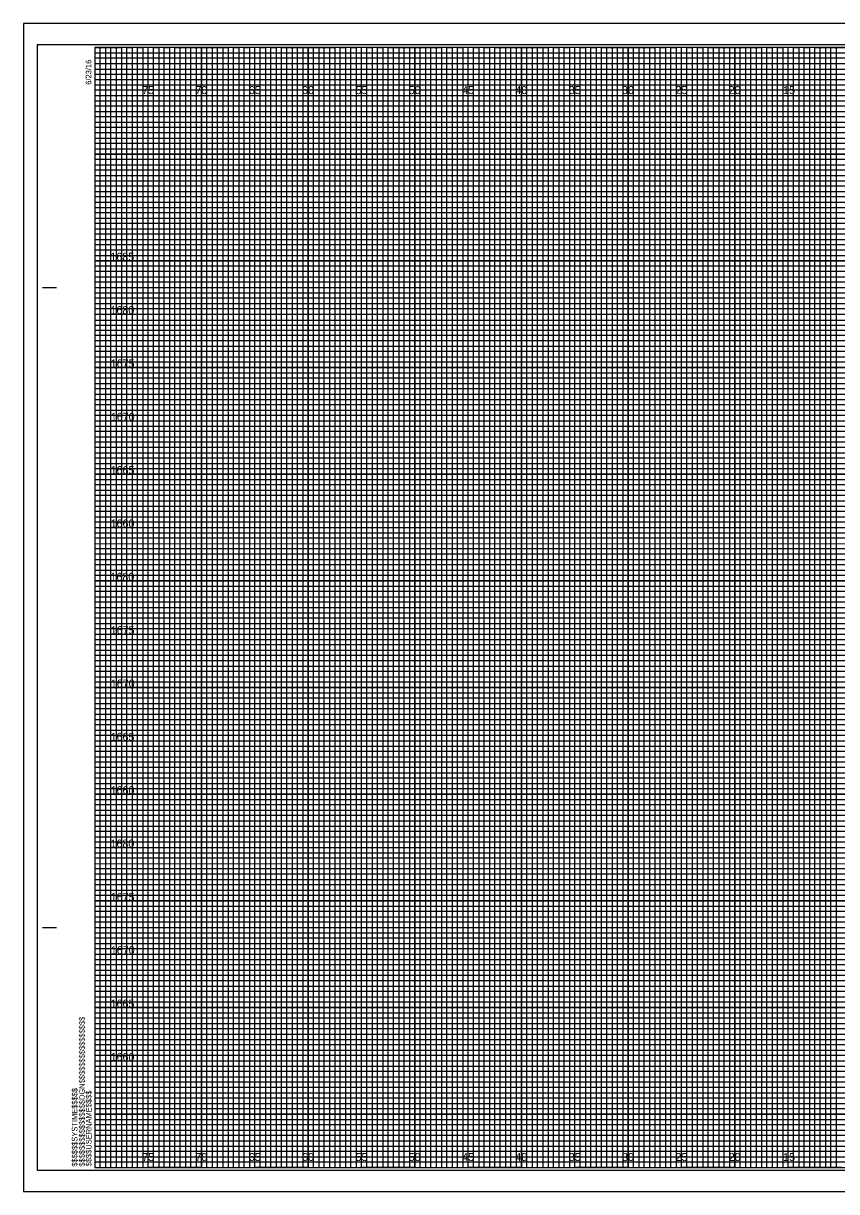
# Model space of a CAD drawing. Extents: x -7 to 162, y -2 to 327.
# Drawn here: x -6.7 to 69.5, y 217.7 to 327.2 of the extents above; entities that cross this region are included whole.
import ezdxf

# ---------------------------------------------------------------- set-up
doc = ezdxf.new("R2010")
doc.units = 0
for name, color, linetype in [('Raster_Level_0', 7, 'Continuous'), ('Scratch_Level_3', 7, 'Continuous'), ('Sheet Cross Section CELL', 7, 'Continuous'), ('Sheet Cross Section Grid Major CELL', 7, 'Continuous'), ('Sheet Cross Section Grid Middle CELL', 7, 'Continuous'), ('Sheet Cross Section Grid Minor 1 CELL', 7, 'Continuous'), ('Sheet Cross Section Grid Minor 2 CELL', 7, 'Continuous'), ('Sheet Cutting Line CELL', 7, 'Continuous'), ('Sheet DOT Grid CELL', 7, 'Continuous'), ('Sheet Plot Border Inside CELL', 7, 'Continuous'), ('Sheet Plot Border Outside CELL', 7, 'Continuous')]:
    doc.layers.add(name, color=color, linetype=linetype)

msp = doc.modelspace()

# ---------------------------------------------------------------- linework, layer by layer
at = {"layer": 'Sheet Cross Section CELL'}
for p, q in [((-4.9, 302.5), (-3.65, 302.5)), ((-4.85, 302.5), (-3.6, 302.5)), ((-4.9, 242.5), (-3.65, 242.5)), ((-4.85, 242.5), (-3.6, 242.5)), ((0, 220), (0, 220)), ((0, 220), (0, 220)), ((0, 220), (0, 220)), ((0, 220), (0, 220)), ((0, 220), (0, 220)), ((0, 220), (0, 220)), ((0, 220), (0, 220))]:
    msp.add_line(p, q, dxfattribs=at)
msp.add_lwpolyline([(160, 325), (0, 325), (0, 220), (160, 220)], close=True, dxfattribs=at)
at = {"layer": 'Sheet Cross Section Grid Major CELL'}
for p, q in [((5, 325), (0, 325)), ((5, 220), (5, 325)), ((15, 325), (10, 325)), ((10, 325), (10, 220)), ((15, 220), (15, 325)), ((25, 325), (20, 325)), ((20, 325), (20, 220)), ((25, 220), (25, 325)), ((35, 325), (30, 325)), ((30, 325), (30, 220)), ((35, 220), (35, 325)), ((45, 325), (40, 325)), ((40, 325), (40, 220)), ((45, 220), (45, 325)), ((55, 325), (50, 325)), ((50, 325), (50, 220)), ((55, 220), (55, 325)), ((65, 325), (60, 325)), ((60, 325), (60, 220)), ((65, 220), (65, 325)), ((10, 220), (5, 220)), ((20, 220), (15, 220)), ((30, 220), (25, 220)), ((40, 220), (35, 220)), ((50, 220), (45, 220)), ((60, 220), (55, 220)), ((70, 220), (65, 220))]:
    msp.add_line(p, q, dxfattribs=at)
for points in [[(0, 320), (160, 320), (160, 315), (0, 315)], [(0, 310), (160, 310), (160, 305), (0, 305)], [(0, 300), (160, 300), (160, 295), (0, 295)], [(0, 290), (160, 290), (160, 285), (0, 285)], [(0, 280), (160, 280), (160, 275), (0, 275)], [(0, 270), (160, 270), (160, 265), (0, 265)], [(0, 260), (160, 260), (160, 255), (0, 255)], [(0, 250), (160, 250), (160, 245), (0, 245)], [(0, 240), (160, 240), (160, 235), (0, 235)], [(0, 230), (160, 230), (160, 225), (0, 225)]]:
    msp.add_lwpolyline(points, dxfattribs=at)
at = {"layer": 'Sheet Cross Section Grid Middle CELL'}
for points in [[(0, 325), (2.5, 325), (2.5, 220), (7.5, 220), (7.5, 325), (12.5, 325), (12.5, 220), (17.5, 220), (17.5, 325), (22.5, 325), (22.5, 220), (27.5, 220), (27.5, 325), (32.5, 325), (32.5, 220), (37.5, 220), (37.5, 325), (42.5, 325), (42.5, 220), (47.5, 220), (47.5, 325), (52.5, 325), (52.5, 220), (57.5, 220), (57.5, 325), (62.5, 325), (62.5, 220), (67.5, 220), (67.5, 325), (72.5, 325)], [(0, 322.5), (137.5, 322.5)], [(0, 312.5), (160, 312.5), (160, 317.5), (0, 317.5)], [(0, 302.5), (160, 302.5), (160, 307.5), (0, 307.5)], [(0, 292.5), (160, 292.5), (160, 297.5), (0, 297.5)], [(0, 282.5), (160, 282.5), (160, 287.5), (0, 287.5)], [(0, 272.5), (160, 272.5), (160, 277.5), (0, 277.5)], [(0, 262.5), (160, 262.5), (160, 267.5), (0, 267.5)], [(0, 252.5), (160, 252.5), (160, 257.5), (0, 257.5)], [(0, 242.5), (160, 242.5), (160, 247.5), (0, 247.5)], [(0, 232.5), (160, 232.5), (160, 237.5), (0, 237.5)], [(0, 222.5), (160, 222.5), (160, 227.5), (0, 227.5)]]:
    msp.add_lwpolyline(points, dxfattribs=at)
at = {"layer": 'Sheet Cross Section Grid Minor 1 CELL'}
for p, q in [((0, 324.5), (130, 324.5)), ((130, 323.99), (0, 323.99)), ((0, 323.99), (0, 323.5)), ((0, 323.5), (130, 323.5)), ((130, 322.94), (0, 322.94)), ((0, 322.94), (0, 322)), ((0, 322), (160, 322))]:
    msp.add_line(p, q, dxfattribs=at)
for points in [[(0, 321.5), (135, 321.5), (160, 321.5), (160, 321), (0, 321)], [(0, 320.5), (160, 320.5), (160, 319.5), (0, 319.5)], [(0, 319), (160, 319), (160, 318.5), (0, 318.49)], [(0, 318), (160, 318), (160, 317), (0, 317)], [(0, 316.5), (160, 316.5), (160, 316), (0, 316)], [(0, 315.5), (160, 315.5), (160, 314.5), (0, 314.5)], [(0, 314), (160, 314), (160, 313.5), (0, 313.5)], [(0, 313), (160, 313), (160, 312), (0, 312)], [(0, 311.5), (160, 311.5), (160, 311), (0, 311)], [(0, 310.5), (160, 310.5), (160, 309.5), (0, 309.5)], [(0, 309), (160, 309), (160, 308.5), (0, 308.5)], [(0, 308), (160, 308), (160, 306.98), (160, 306.5), (160, 306), (0, 306)], [(0, 307), (160, 307), (160, 306.5), (0, 306.5)], [(0, 305.5), (160, 305.5), (160, 304.5), (0, 304.51)], [(0, 304.51), (160, 304.5), (160, 304), (0, 304)], [(0, 303.5), (160, 303.5), (160, 303), (0, 303)], [(0, 302), (160, 302), (160, 301.5), (0, 301.5)], [(0, 301), (160, 301), (160, 300.5), (0, 300.5)], [(-0.04, 299.44), (160, 299.44), (160, 298.94), (-0.04, 298.94)], [(0, 298.5), (160, 298.5), (160, 298), (0, 298)], [(0, 297), (160, 297), (160, 296.5), (0, 296.5)], [(0, 296), (160, 296), (160, 295.5), (0, 295.5)], [(0, 294.5), (160, 294.5), (160, 294), (0, 294)], [(0, 293.5), (160, 293.5), (160, 293), (0, 293)], [(0, 292), (160, 292), (160, 291.5), (0, 291.5)], [(0, 291), (160, 291), (160, 290.5), (0, 290.5)], [(0, 289.5), (160, 289.5), (160, 288.99), (0, 289)], [(0, 288.5), (160, 288.5), (160, 288), (0, 288)], [(0, 287), (160, 287), (160, 286.5), (0, 286.5)], [(0, 286), (160, 286), (160, 285.5), (0, 285.5)], [(0, 284.5), (160, 284.5), (160, 284), (0, 284)], [(0, 283.5), (160, 283.5), (160, 283), (0, 283)], [(0, 282), (160, 282), (160, 281.5), (0, 281.5)], [(0, 281), (160, 281), (160, 280.5), (0, 280.5)], [(0, 279.5), (160, 279.5), (160, 279), (0, 279)], [(0, 278.5), (160.03, 278.45), (160, 278), (0, 278)], [(0, 277), (160, 277), (160, 276.5), (0, 276.5)], [(0, 276), (160, 276), (160, 275.5), (0, 275.5)], [(0, 274.5), (160, 274.5), (160, 274), (0, 274)], [(0, 273.5), (160, 273.5), (160, 273), (0, 273)], [(0, 272), (160, 272), (160, 271.5), (0, 271.5)], [(0, 271), (160, 271), (160, 270.5), (0, 270.5)], [(0, 269.5), (160, 269.5), (160, 269), (0, 269)], [(0, 268.5), (160, 268.5), (160, 268), (0, 268)], [(0, 267), (160, 267), (160, 266.5), (0, 266.5)], [(0, 266), (160, 266), (160, 265.5), (0, 265.5)], [(0, 264.5), (160, 264.5), (160, 264), (0, 264)], [(0, 263.5), (160, 263.5), (160, 263), (0, 263)], [(0, 262), (160, 262), (160, 261.5), (0, 261.5)], [(0, 261), (160, 261), (160, 260.5), (0, 260.5)], [(0, 259.5), (160, 259.5), (160, 258.99), (0, 259)], [(0, 258.5), (160, 258.5), (160, 258), (0, 258)], [(0, 257), (160, 257), (160, 256.5), (0, 256.5)], [(0, 256), (160, 256), (160, 255.5), (0, 255.5)], [(0, 254.5), (160, 254.5), (160, 254), (0, 254)], [(0, 253.5), (160, 253.5), (160, 253), (0, 253)], [(0, 252), (160, 252), (160, 251.5), (0, 251.5)], [(0, 251), (160, 251), (160, 250.5), (0, 250.5)], [(0, 249.5), (160, 249.5), (160, 249), (0, 249)], [(0, 248.5), (160.03, 248.46), (160, 248), (0, 248)], [(0, 247), (160, 247), (160, 246.5), (0, 246.5)], [(0, 246), (160, 246), (160, 245.5), (0, 245.5)], [(0, 244.5), (160, 244.5), (160, 244), (0, 244)], [(0, 243.5), (160, 243.5), (160, 243), (0, 243)], [(0, 242), (160, 242), (160, 241.5), (0, 241.5)], [(0, 241), (160, 241), (160, 240.5), (0, 240.5)], [(0, 239.5), (160, 239.5), (160, 239), (0, 239)], [(0, 238.5), (160, 238.5), (160, 238), (0, 238)], [(0, 237), (160, 237), (160, 236.5), (0, 236.5)], [(0, 236), (160, 236), (160, 235.5), (0, 235.5)], [(0, 234.5), (160, 234.5), (160, 234), (0, 234)], [(0, 233.5), (160, 233.5), (160, 233), (0, 233)], [(0, 232), (160, 232), (160, 231.5), (0, 231.5)], [(0, 231), (160, 231), (160, 230.5), (0, 230.5)], [(0, 229.5), (160, 229.5), (160, 229), (0, 229)], [(0, 228.5), (160, 228.5), (160, 228), (0, 228)], [(0, 227), (160, 227), (160, 226.5), (0, 226.5)], [(0, 226), (160, 226), (160, 225.5), (0, 225.5)], [(0, 224.5), (160, 224.5), (160, 224), (0, 224)], [(0, 223.5), (160, 223.5), (160, 223), (0, 223)], [(0, 222), (160, 222), (160, 221.5), (0, 221.5)], [(0, 221), (160, 221), (160, 220.5), (0, 220.5)]]:
    msp.add_lwpolyline(points, dxfattribs=at)
at = {"layer": 'Sheet Cross Section Grid Minor 2 CELL'}
for points in [[(0, 220), (0.5, 220), (0.5, 325), (1, 325), (1, 220)], [(1, 220), (1.5, 220), (1.5, 325), (2, 325), (2, 220)], [(2.5, 220), (3, 220), (3, 325), (3.5, 325), (3.5, 220)], [(3.5, 220), (4, 220), (4, 325), (4.5, 325), (4.5, 220)], [(5, 220), (5.5, 220), (5.5, 325), (6, 325), (6, 220)], [(6, 220), (6.5, 220), (6.5, 325), (7, 325), (7, 220)], [(7.5, 220), (8, 220), (8, 325), (8.5, 325), (8.5, 220)], [(8.5, 220), (9, 220), (9, 325), (9.5, 325), (9.5, 220)], [(10, 220), (10.5, 220), (10.5, 325), (11, 325), (11, 220)], [(11, 220), (11.5, 220), (11.5, 325), (12, 325), (12, 220)], [(12.5, 220), (13, 220), (13, 325), (13.5, 325), (13.5, 220)], [(13.5, 220), (14, 220), (14, 325), (14.5, 325), (14.5, 220)], [(15, 220), (15.5, 220), (15.5, 325), (16, 325), (16, 220)], [(16, 220), (16.5, 220), (16.5, 325), (17, 325), (17, 220)], [(17.5, 220), (18, 220), (18, 325), (18.5, 325), (18.5, 220)], [(18.5, 220), (19, 220), (19, 325), (19.5, 325), (19.5, 220)], [(20, 220), (20.5, 220), (20.5, 325), (21, 325), (21, 220)], [(21, 220), (21.5, 220), (21.5, 325), (22, 325), (22, 220)], [(22.5, 220), (23, 220), (23, 325), (23.5, 325), (23.5, 220)], [(23.5, 220), (24, 220), (24, 325), (24.5, 325), (24.5, 220)], [(25, 220), (25.5, 220), (25.5, 325), (26, 325), (26, 220)], [(26, 220), (26.5, 220), (26.5, 325), (27, 325), (27, 220)], [(27.5, 220), (28, 220), (28, 325), (28.5, 325), (28.5, 220)], [(28.5, 220), (29, 220), (29, 325), (29.5, 325), (29.5, 220)], [(30, 220), (30.5, 220), (30.5, 325), (31, 325), (31, 220)], [(31, 220), (31.5, 220), (31.5, 325), (32, 325), (32, 220)], [(32.5, 220), (33, 220), (33, 325), (33.5, 325), (33.5, 220)], [(33.5, 220), (34, 220), (34, 325), (34.5, 325), (34.5, 220)], [(35, 220), (35.5, 220), (35.5, 325), (36, 325), (36, 220)], [(36, 220), (36.5, 220), (36.5, 325), (37, 325), (37, 220)], [(37.5, 220), (38, 220), (38, 325), (38.5, 325), (38.5, 220)], [(38.5, 220), (39, 220), (39, 325), (39.5, 325), (39.5, 220)], [(40, 220), (40.5, 220), (40.5, 325), (41, 325), (41, 220)], [(41, 220), (41.5, 220), (41.5, 325), (42, 325), (42, 220)], [(42.5, 220), (43, 220), (43, 325), (43.5, 325), (43.5, 220)], [(43.5, 220), (44, 220), (44, 325), (44.5, 325), (44.5, 220)], [(45, 220), (45.5, 220), (45.5, 325), (46, 325), (46, 220)], [(46, 220), (46.5, 220), (46.5, 325), (47, 325), (47, 220)], [(47.5, 220), (48, 220), (48, 325), (48.5, 325), (48.5, 220)], [(48.5, 220), (49, 220), (49, 325), (49.5, 325), (49.5, 220)], [(50, 220), (50.5, 220), (50.5, 325), (51, 325), (51, 220)], [(51, 220), (51.5, 220), (51.5, 325), (52, 325), (52, 220)], [(52.5, 220), (53, 220), (53, 325), (53.5, 325), (53.5, 220)], [(53.5, 220), (54, 220), (54, 325), (54.5, 325), (54.5, 220)], [(55, 220), (55.5, 220), (55.5, 325), (56, 325), (56, 220)], [(56, 220), (56.5, 220), (56.5, 325), (57, 325), (57, 220)], [(57.5, 220), (58, 220), (58, 325), (58.5, 325), (58.5, 220)], [(58.5, 220), (59, 220), (59, 325), (59.5, 325), (59.5, 220)], [(60, 220), (60.5, 220), (60.5, 325), (61, 325), (61, 220)], [(61, 220), (61.5, 220), (61.5, 325), (62, 325), (62, 220)], [(62.5, 220), (63, 220), (63, 325), (63.5, 325), (63.5, 220)], [(63.5, 220), (64, 220), (64, 325), (64.5, 325), (64.5, 220)], [(65, 220), (65.5, 220), (65.5, 325), (66, 325), (66, 220)], [(66, 220), (66.5, 220), (66.5, 325), (67, 325), (67, 220)], [(67.5, 220), (68, 220), (68, 325), (68.5, 325), (68.5, 220)], [(68.5, 220), (69, 220), (69, 325), (69.5, 325), (69.5, 220)]]:
    msp.add_lwpolyline(points, dxfattribs=at)
at = {"layer": 'Sheet Cutting Line CELL'}
for p, q in [((161.65, 327.25), (-6.7, 327.25)), ((-6.7, 327.25), (-6.7, 217.75)), ((-6.7, 217.75), (161.65, 217.75))]:
    msp.add_line(p, q, dxfattribs=at)
at = {"layer": 'Sheet DOT Grid CELL'}
for p, q in [((5, 220), (5, 325)), ((10, 220), (10, 325)), ((15, 220), (15, 325)), ((20, 220), (20, 325)), ((25, 220), (25, 325)), ((30, 220), (30, 325)), ((35, 220), (35, 325)), ((40, 220), (40, 325)), ((45, 220), (45, 325)), ((50, 220), (50, 325)), ((55, 220), (55, 325)), ((60, 220), (60, 325)), ((65, 220), (65, 325)), ((0, 320), (160, 320)), ((0, 315), (160, 315)), ((0, 310), (160, 310)), ((0, 305), (160, 305)), ((0, 300), (160, 300)), ((0, 295), (160, 295)), ((0, 290), (160, 290)), ((0, 285), (160, 285)), ((0, 280), (160, 280)), ((0, 275), (160, 275)), ((0, 270), (160, 270)), ((0, 265), (160, 265)), ((0, 260), (160, 260)), ((0, 255), (160, 255)), ((0, 250), (160, 250)), ((0, 245), (160, 245)), ((0, 240), (160, 240)), ((0, 235), (160, 235)), ((0, 230), (160, 230)), ((0, 225), (160, 225))]:
    msp.add_line(p, q, dxfattribs=at)
at = {"layer": 'Sheet Plot Border Inside CELL'}
msp.add_lwpolyline([(-5.4, 219.75), (161.2, 219.75), (161.2, 325.25), (-5.4, 325.25)], close=True, dxfattribs=at)
at = {"layer": 'Sheet Plot Border Outside CELL'}
msp.add_lwpolyline([(-6.7, 217.75), (161.65, 217.75), (161.65, 327.25), (-6.7, 327.25)], close=True, dxfattribs=at)

# ---------------------------------------------------------------- texts
at = {"layer": 'Raster_Level_0'}
for s, p in [('75', (4.44, 320.62)), ('70', (9.43, 320.62)), ('65', (14.44, 320.62)), ('60', (19.43, 320.62)), ('55', (24.44, 320.62)), ('50', (29.43, 320.62)), ('45', (34.44, 320.62)), ('40', (39.43, 320.62)), ('35', (44.44, 320.62)), ('30', (49.43, 320.62)), ('25', (54.44, 320.62)), ('20', (59.43, 320.62)), ('15', (64.53, 320.62)), ('75', (4.44, 220.62)), ('70', (9.43, 220.62)), ('65', (14.44, 220.62)), ('60', (19.43, 220.62)), ('55', (24.44, 220.62)), ('50', (29.43, 220.62)), ('45', (34.44, 220.62)), ('40', (39.43, 220.62)), ('35', (44.44, 220.62)), ('30', (49.43, 220.62)), ('25', (54.44, 220.62)), ('20', (59.43, 220.62)), ('15', (64.53, 220.62))]:
    msp.add_text(s, height=0.75, dxfattribs=at).set_placement(p)
at = {"layer": 'Scratch_Level_3'}
for s, p in [('1685', (1.46, 305)), ('1680', (1.47, 300)), ('1675', (1.49, 295)), ('1670', (1.5, 290)), ('1665', (1.48, 285)), ('1660', (1.48, 280)), ('1680', (1.47, 275)), ('1675', (1.49, 270)), ('1670', (1.5, 265)), ('1665', (1.48, 260)), ('1660', (1.48, 255)), ('1680', (1.47, 250)), ('1675', (1.49, 245)), ('1670', (1.5, 240)), ('1665', (1.48, 235)), ('1660', (1.48, 230))]:
    msp.add_text(s, height=0.75, dxfattribs=at).set_placement(p)
at = {"layer": 'Sheet Cross Section CELL'}
for s, p in [('6/23/16', (-0.33, 321.5)), ('$$$$$$$$$$$$$$$$DGN$$$$$$$$$$$$$$$$', (-0.94, 220.09)), ('$$$$$$SYSTIME$$$$$', (-1.63, 220.09)), ('$$$$USERNAME$$$$', (-0.31, 220.12))]:
    msp.add_text(s, height=0.525, rotation=90, dxfattribs=at).set_placement(p)

doc.saveas('drawing.dxf')
